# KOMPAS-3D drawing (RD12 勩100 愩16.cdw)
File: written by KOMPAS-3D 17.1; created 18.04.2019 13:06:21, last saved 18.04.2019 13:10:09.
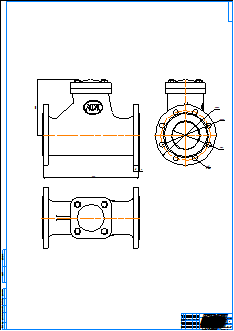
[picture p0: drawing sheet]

Sheet 1: A0, portrait

Title block, sheet 1: name: RD12 Ду100 Ру16; material: Внимание! Данный продукт является объектом авторского права ООО «Торговый Дом АДЛ». / Запрещается изменение, копирование, распространение / (в том числе путем копирования на другие сайты и ресурсы в Интернете) / или любое иное использование информации и объектов без предварительного / согласия правообладателя (ООО «Торговый Дом АДЛ»).; mass: 53,38; sheets: 1; organisation: ООО "Торговый дом АДЛ"; sheet format: A0

Views: Вид 1, Проекционный вид 2, Проекционный вид 3
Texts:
  user
Dimensions and other numbers on the sheet: 19; 3; 344; 200; 180; 220; 100; 8 отв.; 1:1; 1; 53,38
